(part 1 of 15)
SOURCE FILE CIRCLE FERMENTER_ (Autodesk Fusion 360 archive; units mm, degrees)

design "SOURCE FILE CIRCLE FERMENTER" references "rotary+encoder_14mm_hole_spc", "MODULO RISCALDATORE", "MAGNETE 10x3", "Vite a broccia con testa incassata ed esagono incassato ANSI B18.3.1M - M3x0.5 x 8 Designazione acciaio 2 Radente", "ruthex_RX-M3x4", "GN 1-4 h65.ipt", "Schermo elink", "MODULO RISCALDATORE 1 ventola", "DHT22 Module v3"
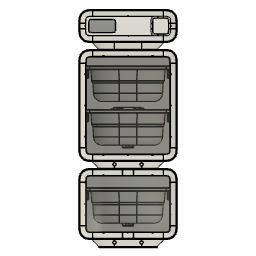
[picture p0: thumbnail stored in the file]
component_insert "Inserimento componente1"
component_insert "Inserimento componente2"
sketch "Schizzo1" plane through (0, 0, 0) normal (0, 0, 1) x axis (1, 0, 0)
  line L1 (-160, 90) -> (160, 90)
  line L2 (-160, -90) -> (-160, 90)
  line L3 (160, -90) -> (-160, -90)
  line L4 (160, 90) -> (160, -90)
  line L5 (-160, -90) -> (160, 90)
  line L6 (160, -90) -> (-160, 90)
  point P6 (0, 0)
  point P1 (0, 0)
  point P3 (-160, 90)
  point P4 (-160, -90)
  horizontal L1
  perpendicular L1 L2
  parallel L1 L3
  parallel L2 L4
  coincident L5 P6
  coincident L6 P6
  coincident P1 P6
  dimension "d1" distance P3 P4 = 180
  dimension "d2" distance L2 L4 = 320
  dimension "TOLL_SPORTELLO" distance = 0.5
extrude "Estrusione1" new body sketch "Schizzo1" profile of L1 L2 L3 L4 along normal blind 116.5 (= "86.50 mm + 30 mm")
extrude "Estrusione2" add of existing geometry blind 88.5 (= "58.50 mm + 30 mm")
sketch "Schizzo1" plane through (160, 0, 0) normal (1, 0, 0) x axis (0, 1, 0)
  line L1 (90, 116.5) -> (90, -88.5)
  line L2 (-90, 116.5) -> (90, 116.5)
  line L3 (-90, -88.5) -> (-90, 116.5)
  line L4 (90, -88.5) -> (-90, -88.5)
  line L5 (0, -88.5) -> (0, 116.5)
  line L6 (-90, 14) -> (90, 14)
  curve K1 (-90, -73.5) -> (-90, -63.5)
  curve K2 (-90, -81) -> (-90, -73.5)
  curve K3 (-82.5, -88.5) -> (-90, -81)
  curve K4 (-75, -88.5) -> (-82.5, -88.5)
  curve K5 (-65, -88.5) -> (-75, -88.5)
  curve K6 (-65, -88.5) -> (-90, -63.5)
  curve K7
  curve K8 (-90, 101.5) -> (-90, 91.5)
  curve K9 (-90, 109) -> (-90, 101.5)
  curve K10 (-82.5, 116.5) -> (-90, 109)
  curve K11 (-75, 116.5) -> (-82.5, 116.5)
  curve K12 (-65, 116.5) -> (-75, 116.5)
  curve K13
  curve K14 (90, 101.5) -> (90, 91.5)
  curve K15 (90, 109) -> (90, 101.5)
  curve K16 (82.5, 116.5) -> (90, 109)
  curve K17 (75, 116.5) -> (82.5, 116.5)
  curve K18 (65, 116.5) -> (75, 116.5)
  curve K19 (65, -88.5) -> (90, -63.5)
  curve K20 (90, -73.5) -> (90, -63.5)
  curve K21 (90, -81) -> (90, -73.5)
  curve K22 (82.5, -88.5) -> (90, -81)
  curve K23 (75, -88.5) -> (82.5, -88.5)
  curve K24 (65, -88.5) -> (75, -88.5)
  line L7 (-90, 91.5) -> (-90, -63.5)
  line L8 (65, 116.5) -> (-65, 116.5)
  line L9 (90, -63.5) -> (90, 91.5)
  line L10 (-65, -88.5) -> (65, -88.5)
  point P6 (0, 116.5)
  point P7 (0, -88.5)
  point P8 (90, 14)
  point P9 (-90, 14)
  point P10 (-90, -63.5)
  point P11 (-90, -73.5)
  point P12 (-90, -81)
  point P13 (-82.5, -88.5)
  point P14 (-75, -88.5)
  point P15 (-65, -88.5)
  point P16 (-90, 91.5)
  point P17 (-65, 116.5)
  point P28 (90, -63.5)
  point P29 (65, -88.5)
  point P22 (90, 91.5)
  point P23 (65, 116.5)
  point P5 (-90, -88.5)
  midpoint L2 P6
  midpoint L4 P7
  midpoint L1 P8
  midpoint L3 P9
  coincident L3 P10
  coincident L3 P11
  coincident L3 P12
  coincident L4 P13
  coincident L4 P14
  coincident L4 P15
  symmetric L6 P10 P16
  symmetric L6 P15 P17
  symmetric L5 P10 P28
  symmetric L5 P15 P29
  symmetric L5 K6 K19
  symmetric L5 P16 P22
  symmetric L5 P17 P23
  symmetric L5 K7 K13
  dimension "d7" distance P5 P13 = 7.5
  dimension "d8" distance P5 P12 = 7.5 (= "d7")
  dimension "d9" distance P5 P14 = 15
  dimension "d10" distance P5 P11 = 15 (= "d9")
  dimension "d11" distance P5 P15 = 25
  dimension "d12" distance P5 P10 = 25 (= "d11")
  dimension "d1108" = 148
extrude "Estrusione1" new body sketch "Schizzo1" profile of K6 K7 K13 K19 L7 L8 L9 L10 against normal blind 320
sketch "Schizzo2" plane through (160, 0, 0) normal (1, 0, 0) x axis (0, 1, 0)
  curve K1 (65, 116.5) -> (90, 91.5)
  line L1 (-65, 116.5) -> (65, 116.5)
  curve K2 (-65, 116.5) -> (-90, 91.5)
  line L2 (-90, -63.5) -> (-90, 91.5)
  curve K3 (-65, -88.5) -> (-90, -63.5)
  line L3 (65, -88.5) -> (-65, -88.5)
  curve K4 (65, -88.5) -> (90, -63.5)
  line L4 (90, 91.5) -> (90, -63.5)
  line L5 (-65, 114.1) -> (65, 114.1)
  curve K5 (-65, 114.1) -> (-87.6, 91.5)
  line L6 (-87.6, -63.5) -> (-87.6, 91.5)
  curve K6 (-65, -86.1) -> (-87.6, -63.5)
  line L7 (65, -86.1) -> (-65, -86.1)
  curve K7 (65, -86.1) -> (87.6, -63.5)
  line L8 (87.6, 91.5) -> (87.6, -63.5)
  curve K8 (65, 114.1) -> (87.6, 91.5)
  dimension "d15" = -2.4
extrude "Estrusione2" cut sketch "Schizzo2" profile of K8 L5 K5 L6 K6 K7 L7 L8 against normal blind 320
sketch "Schizzo3" plane through (0, -90, 0) normal (0, -1, 0) x axis (1, 0, 0)
  line L1 (160, 91.5) -> (160, -63.5)
  line L2 (-160, 91.5) -> (160, 91.5)
  line L3 (-160, -63.5) -> (-160, 91.5)
  line L4 (160, -63.5) -> (-160, -63.5)
  line L5 (-130, 86.5) -> (130, 86.5)
  line L6 (-130, -58.5) -> (-130, 86.5)
  line L7 (130, -58.5) -> (-130, -58.5)
  line L8 (130, 86.5) -> (130, -58.5)
  line L9 (-160, 116.5) -> (160, 116.5)
  line L10 (-160, 91.5) -> (-160, -63.5)
  line L11 (160, 91.5) -> (160, -63.5)
  line L12 (-160, -88.5) -> (160, -88.5)
  horizontal L5
  vertical L6
  horizontal L7
  vertical L8
  dimension "d18" distance L6 L10 = 30
  dimension "d19" distance L5 L9 = 30
  dimension "d20" distance L8 L11 = 30 (= "d18")
  dimension "d21" distance L7 L12 = 30 (= "d19")
extrude "Estrusione3" cut sketch "Schizzo3" profile of L5 L6 L7 L8 against normal blind 331.457
fillet "Raccordo1" radius 22
sketch "Schizzo4" plane through (0, 0, 116.5) normal (0, 0, 1) x axis (-1, 0, 0)
  line L1 (-160, -65) -> (-160, 65)
  line L2 (160, -65) -> (-160, -65)
  line L3 (160, 65) -> (160, -65)
  line L4 (-160, 65) -> (160, 65)
  line L5 (-130, 60) -> (130, 60)
  line L6 (-130, -60) -> (-130, 60)
  line L7 (130, -60) -> (-130, -60)
  line L8 (130, 60) -> (130, -60)
  line L9 (-160, 65) -> (-160, 90)
  line L10 (160, 65) -> (-160, 65)
  line L11 (160, 65) -> (160, 90)
  line L12 (-160, 90) -> (160, 90)
  line L13 (-160, -65) -> (-160, -90)
  line L14 (160, -90) -> (-160, -90)
  line L15 (160, -90) -> (160, -65)
  line L16 (-160, -65) -> (160, -65)
  horizontal L5
  vertical L6
  horizontal L7
  vertical L8
  dimension "d26" distance L3 L8 = 30
  dimension "d29" distance L1 L6 = 30
extrude "Estrusione4" cut sketch "Schizzo4" profile of L2 L4 L5 L6 L7 L8 L10 L16 against normal blind 273.897
fillet "Raccordo2" radius 22
sketch "Schizzo5" plane through (-160, 0, 0) normal (-1, 0, 0) x axis (0, -1, 0)
  curve K1 (-65, 114.1) -> (-87.6, 91.5)
  line L1 (65, 114.1) -> (-65, 114.1)
  curve K2 (87.6, 91.5) -> (65, 114.1)
  line L2 (87.6, -63.5) -> (87.6, 91.5)
  curve K3 (65, -86.1) -> (87.6, -63.5)
  line L3 (-65, -86.1) -> (65, -86.1)
  curve K4 (-87.6, -63.5) -> (-65, -86.1)
  line L4 (-87.6, 91.5) -> (-87.6, -63.5)
  curve K5 (-90, 91.5) -> (-65, 116.5)
  line L5 (-90, -63.5) -> (-90, 91.5)
  curve K6 (-65, -88.5) -> (-90, -63.5)
  line L6 (65, -88.5) -> (-65, -88.5)
  curve K7 (90, -63.5) -> (65, -88.5)
  line L7 (90, 91.5) -> (90, -63.5)
  curve K8 (65, 116.5) -> (90, 91.5)
  line L8 (-65, 116.5) -> (65, 116.5)
  line L9 (-65, 91.5) -> (-65, 114.1)
  line L10 (-87.6, 91.5) -> (-65, 91.5)
  line L11 (-84.5312, 111.0312) -> (-65, 91.5)
  line L12 (-77.8844, 104.3844) -> (-82.8342, 109.3342)
  curve K9 (-80.0057, 102.2631) -> (-77.8844, 104.3844)
  curve K10 (-82.1271, 100.1418) -> (-80.0057, 102.2631)
  curve K11 (-85.6626, 100.8489) -> (-82.1271, 100.1418)
  curve K12 (-87.4513, 97.5) -> (-85.6626, 100.8489)
  curve K13 (-87.577, 94.5) -> (-87.4513, 97.5)
  curve K14 (-87.6, 91.5) -> (-87.577, 94.5)
  curve K15 (-87.6, 91.5) -> (-77.8844, 104.3844)
  line L13 (-90.4063, 91.8626) -> (-77.8844, 104.3844)
  curve K16 (-65, 114.1) -> (-77.8844, 104.3844)
  curve K17 (-75.7631, 106.5057) -> (-77.8844, 104.3844)
  curve K18 (-73.6418, 108.6271) -> (-75.7631, 106.5057)
  curve K19 (-74.3489, 112.1626) -> (-73.6418, 108.6271)
  curve K20 (-71, 113.9513) -> (-74.3489, 112.1626)
  curve K21 (-68, 114.077) -> (-71, 113.9513)
  curve K22 (-65, 114.1) -> (-68, 114.077)
  line L14 (-87.6, 14) -> (87.6, 14)
  line L15 (0, -86.1) -> (0, 114.1)
  curve K23 (65, 114.1) -> (77.8844, 104.3844)
  curve K24 (75.7631, 106.5057) -> (77.8844, 104.3844)
  curve K25 (73.6418, 108.6271) -> (75.7631, 106.5057)
  curve K26 (74.3489, 112.1626) -> (73.6418, 108.6271)
  curve K27 (71, 113.9513) -> (74.3489, 112.1626)
  curve K28 (68, 114.077) -> (71, 113.9513)
  curve K29 (65, 114.1) -> (68, 114.077)
  curve K30 (87.6, 91.5) -> (77.8844, 104.3844)
  curve K31 (80.0057, 102.2631) -> (77.8844, 104.3844)
  curve K32 (82.1271, 100.1418) -> (80.0057, 102.2631)
  curve K33 (85.6626, 100.8489) -> (82.1271, 100.1418)
  curve K34 (87.4513, 97.5) -> (85.6626, 100.8489)
  curve K35 (87.577, 94.5) -> (87.4513, 97.5)
  curve K36 (87.6, 91.5) -> (87.577, 94.5)
  curve K37 (-65, -86.1) -> (-77.8844, -76.3844)
  curve K38 (-75.7631, -78.5057) -> (-77.8844, -76.3844)
  curve K39 (-73.6418, -80.6271) -> (-75.7631, -78.5057)
  curve K40 (-74.3489, -84.1626) -> (-73.6418, -80.6271)
  curve K41 (-71, -85.9513) -> (-74.3489, -84.1626)
  curve K42 (-68, -86.077) -> (-71, -85.9513)
  curve K43 (-65, -86.1) -> (-68, -86.077)
  curve K44 (-87.6, -63.5) -> (-77.8844, -76.3844)
  curve K45 (-80.0057, -74.2631) -> (-77.8844, -76.3844)
  curve K46 (-82.1271, -72.1418) -> (-80.0057, -74.2631)
  curve K47 (-85.6626, -72.8489) -> (-82.1271, -72.1418)
  curve K48 (-87.4513, -69.5) -> (-85.6626, -72.8489)
  curve K49 (-87.577, -66.5) -> (-87.4513, -69.5)
  curve K50 (-87.6, -63.5) -> (-87.577, -66.5)
  curve K51 (65, -86.1) -> (77.8844, -76.3844)
  curve K52 (75.7631, -78.5057) -> (77.8844, -76.3844)
  curve K53 (73.6418, -80.6271) -> (75.7631, -78.5057)
  curve K54 (74.3489, -84.1626) -> (73.6418, -80.6271)
  curve K55 (71, -85.9513) -> (74.3489, -84.1626)
  curve K56 (68, -86.077) -> (71, -85.9513)
  curve K57 (65, -86.1) -> (68, -86.077)
  curve K58 (87.6, -63.5) -> (77.8844, -76.3844)
  curve K59 (80.0057, -74.2631) -> (77.8844, -76.3844)
  curve K60 (82.1271, -72.1418) -> (80.0057, -74.2631)
  curve K61 (85.6626, -72.8489) -> (82.1271, -72.1418)
  curve K62 (87.4513, -69.5) -> (85.6626, -72.8489)
  curve K63 (87.577, -66.5) -> (87.4513, -69.5)
  curve K64 (87.6, -63.5) -> (87.577, -66.5)
  line L16 (-90, 91.5) -> (-87.6, 91.5)
  line L17 (-89.7336, 97.5) -> (-89.7336, 91.5)
  line L18 (-86.7336, 97.5) -> (-89.7336, 97.5)
  point P18 (-65, 114.1)
  point P20 (-65, 114.1)
  point P19 (-87.6, 91.5)
  point P22 (-87.6, 91.5)
  point P23 (-84.5312, 111.0312)
  point P24 (-82.8342, 109.3342)
  point P29 (-87.4513, 97.5)
  point P30 (-87.577, 94.5)
  point P26 (-80.0057, 102.2631)
  point P27 (-82.1271, 100.1418)
  point P2 (-87.6, 91.5)
  point P33 (-65, 114.1)
  point P25 (-77.8844, 104.3844)
  point P32 (-77.8844, 104.3844)
  point P39 (87.6, 14)
  point P40 (-87.6, 14)
  point P41 (0, 114.1)
  point P42 (0, -86.1)
  point P51 (87.6, 91.5)
  point P50 (77.8844, 104.3844)
  point P43 (77.8844, 104.3844)
  point P44 (65, 114.1)
  point P65 (-87.6, -63.5)
  point P64 (-77.8844, -76.3844)
  point P57 (-77.8844, -76.3844)
  point P58 (-65, -86.1)
  point P71 (77.8844, -76.3844)
  point P72 (65, -86.1)
  point P78 (77.8844, -76.3844)
  point P79 (87.6, -63.5)
  point P85 (-87.6, 91.5)
  point P11 (-90, 91.5)
  point P86 (-90, 91.5)
  point P87 (-89.7336, 91.5)
  point P89 (-86.7336, 97.5)
  point P28 (-85.6626, 100.8489)
  point P88 (-89.7336, 97.5)
  coincident P18 P20
  perpendicular L1 L9
  coincident P19 P22
  horizontal L10
  coincident K5 P23
  coincident K1 P24
  coincident L11 P24
  parallel L11 L12
  coincident K1 P29
  coincident K1 P30
  perpendicular L12 L13
  coincident P26 L13
  coincident P27 L13
  symmetric P2 L12 P33
  symmetric P25 L12 P32
  symmetric L12 K15 K16
  midpoint L2 P39
  midpoint L4 P40
  midpoint L1 P41
  midpoint L3 P42
  symmetric P2 L15 P51
  symmetric P25 L15 P50
  symmetric K15 L15 K30
  symmetric P32 L15 P43
  symmetric P33 L15 P44
  symmetric K16 L15 K23
  symmetric P2 L14 P65
  symmetric P25 L14 P64
  symmetric K15 L14 K44
  symmetric P32 L14 P57
  symmetric P33 L14 P58
  symmetric K16 L14 K37
  symmetric L14 P43 P71
  symmetric L14 P44 P72
  symmetric L14 K23 K51
  symmetric L14 P50 P78
  symmetric L14 P51 P79
  symmetric L14 K30 K58
  coincident P2 P85
  coincident P11 P86
  coincident L16 P87
  perpendicular L16 L17
  coincident K15 P89
  perpendicular L17 L18
  dimension "d34" angle L10 L11 = 45
  dimension "d35" distance P24 P25 = 7
  dimension "d38" distance P25 P26 = 3
  dimension "d39" distance P25 P27 = 6
  dimension "d40" distance P28 L13 = 3
  dimension "d41" distance P29 P30 = 3
  dimension "d42" distance P22 P30 = 3
  dimension "d43" distance L11 P28 = 8
  dimension "d57" = 5
  dimension "d172" distance P87 P88 = 6
  dimension "d173" distance P88 P89 = 3
  dimension "d174" distance L4 L17 = 2.1336
  dimension "d209" = 7.5 (= "d208")
  dimension "d210" = 15 (= "d207")
  dimension "d211" = 30 (= "d206")
  dimension "d231" = 7
  dimension "d232" = 5
  dimension "d233" = 5
  dimension "d335" = 5
  dimension "d742" = 9
  dimension "d209_1" = 7.5 (= "d208_1")
  dimension "d210_1" = 15 (= "d207_1")
  dimension "d211_1" = 30 (= "d206_1")
  dimension "d231_1" = 7
  dimension "d232_1" = 5
  dimension "d233_1" = 5
  dimension "d335_1" = 5
  dimension "d742_1" = 9
extrude "Estrusione5" add sketch "Schizzo5" profile of K1 K2 K3 K4 L12 K15 K16 K23 K30 K37 K44 K51 K58 against normal blind 320
sketch "Schizzo7" plane through (160, 0, 0) normal (1, 0, 0) x axis (0, 1, 0)
  line L1 (87.6, -63.5) -> (87.6, 91.5)
  curve K1 (77.8844, -76.3844) -> (87.6, -63.5)
  curve K2 (65, -86.1) -> (77.8844, -76.3844)
  line L2 (-65, -86.1) -> (65, -86.1)
  curve K3 (-77.8844, -76.3844) -> (-65, -86.1)
  curve K4 (-87.6, -63.5) -> (-77.8844, -76.3844)
  line L3 (-87.6, 91.5) -> (-87.6, -63.5)
  curve K5 (-77.8844, 104.3844) -> (-87.6, 91.5)
  curve K6 (-65, 114.1) -> (-77.8844, 104.3844)
  line L4 (65, 114.1) -> (-65, 114.1)
  curve K7 (77.8844, 104.3844) -> (65, 114.1)
  curve K8 (87.6, 91.5) -> (77.8844, 104.3844)
  curve K9 (65, 116.5) -> (90, 91.5)
  line L5 (-65, 116.5) -> (65, 116.5)
  curve K10 (-65, 116.5) -> (-90, 91.5)
  line L6 (-90, -63.5) -> (-90, 91.5)
  curve K11 (-65, -88.5) -> (-90, -63.5)
  line L7 (65, -88.5) -> (-65, -88.5)
  curve K12 (65, -88.5) -> (90, -63.5)
  line L8 (90, 91.5) -> (90, -63.5)
  curve K13 (65, -86.1) -> (87.6, -63.5)
  line L9 (65, -86.1) -> (-65, -86.1)
  curve K14 (-65, -86.1) -> (-87.6, -63.5)
  line L10 (-87.6, -63.5) -> (-87.6, 91.5)
  curve K15 (-65, 114.1) -> (-87.6, 91.5)
  line L11 (-65, 114.1) -> (65, 114.1)
  curve K16 (65, 114.1) -> (87.6, 91.5)
  line L12 (87.6, 91.5) -> (87.6, -63.5)
  dimension "d46" = -2.4
extrude "Estrusione6" cut sketch "Schizzo7" profile of K1 K2 K3 K4 K5 K6 K7 K8 K13 K14 K16 K15 against normal blind 52
work_plane "Piano di lavoro1" AlongDistance -30
sketch "Schizzo8" plane through (0, 0, -58.5) normal (0, 0, -1) x axis (-1, 0, 0)
  line L1 (-130, -38) -> (-130, 38)
  line L2 (-160, -65) -> (-108, -65)
  line L3 (-160, 65) -> (-160, -65)
  line L4 (-108, 65) -> (-160, 65)
  line L5 (-160, -87.6) -> (-160, -65)
  line L6 (-108, -65) -> (-160, -65)
  line L7 (-108, -87.6) -> (-108, -65)
  line L8 (-160, -87.6) -> (-108, -87.6)
  line L9 (-108, -87.6) -> (-108, -65)
  line L10 (-160, -87.6) -> (-108, -87.6)
  line L11 (-134, -82.6) -> (-134, -87.6)
  line L12 (-160, -65) -> (-160, -90)
  line L13 (160, -90) -> (-160, -90)
  line L14 (160, -90) -> (160, -65)
  line L15 (-160, -65) -> (160, -65)
  line L16 (-136.5, -82.6) -> (-134, -82.6)
  line L17 (-131.5, -82.6) -> (-134, -82.6)
  curve K1 (-139, -82.6) -> (-134, -82.6)
  curve K2 (-141.5, -85.1) -> (-139, -82.6)
  curve K3 (-155, -87.6) -> (-141.5, -85.1)
  curve K4 (-160, -87.6) -> (-155, -87.6)
  curve K5 (-160, -87.6) -> (-134, -82.6)
  curve K6 (-108, -87.6) -> (-134, -82.6)
  curve K7 (-129, -82.6) -> (-134, -82.6)
  curve K8 (-126.5, -85.1) -> (-129, -82.6)
  curve K9 (-113, -87.6) -> (-126.5, -85.1)
  curve K10 (-108, -87.6) -> (-113, -87.6)
  line L18 (108, -60) -> (-108, -60)
  line L19 (130, 38) -> (130, -38)
  line L20 (-108, 60) -> (108, 60)
  line L21 (160, 65) -> (-108, 65)
  line L22 (160, -65) -> (160, 65)
  line L23 (-108, -65) -> (160, -65)
  arc A1 centre (-108, 38) radius 22 clockwise from (-130, 38) to (-108, 60)
  arc A2 centre (108, -38) radius 22 clockwise from (130, -38) to (108, -60)
  arc A3 centre (108, 38) radius 22 clockwise from (108, 60) to (130, 38)
  arc A4 centre (-108, -38) radius 22 clockwise from (-108, -60) to (-130, -38)
  point P11 (-108, -65)
  point P15 (-108, -65)
  point P14 (-108, -87.6)
  point P16 (-108, -87.6)
  point P10 (-160, -87.6)
  point P17 (-160, -87.6)
  point P18 (-134, -87.6)
  point P30 (-155, -87.6)
  point P32 (-108, -87.6)
  point P19 (-134, -82.6)
  point P31 (-134, -82.6)
  point P26 (-136.5, -82.6)
  point P27 (-131.5, -82.6)
  point P28 (-139, -82.6)
  point P29 (-141.5, -85.1)
  coincident P11 P15
  coincident P14 P16
  coincident P10 P17
  midpoint L8 P18
  perpendicular L8 L11
  perpendicular L11 L16
  perpendicular L11 L17
  coincident L8 P30
  horizontal K1
  symmetric P10 L11 P32
  symmetric P19 L11 P31
  symmetric L11 K5 K6
  dimension "d50" distance P19 L13 = 7.4
  dimension "d51" distance P19 P26 = 2.5
  dimension "d52" distance P19 P27 = 2.5
  dimension "d53" distance P19 P28 = 5
  dimension "d54" distance P19 P29 = 7.5
  dimension "d55" distance L12 P30 = 5
  dimension "d56" distance L10 P29 = 2.5
  dimension "d57" distance P18 P19 = 5
extrude "Estrusione7" add sketch "Schizzo8" profile of L8 L10 K5 K6 against normal blind 145
work_plane "Piano di lavoro2" AlongDistance -30
sketch "Schizzo9" plane through (0, -60, 0) normal (0, -1, 0) x axis (-1, 0, 0)
  line L1 (-130, 88.5) -> (-108, 88.5)
  line L2 (-160, 88.5) -> (160, 88.5)
  line L3 (160, 88.5) -> (-160, 88.5)
  line L4 (0, 81.1) -> (0, 88.5)
  line L5 (-160, 86.1) -> (-160, 63.5)
  line L6 (-108, 63.5) -> (-160, 63.5)
  line L7 (-108, 86.1) -> (-108, 63.5)
  line L8 (-160, 86.1) -> (-108, 86.1)
  curve K1 (-5, 81.1) -> (0, 81.1)
  curve K2 (-7.5, 83.6) -> (-5, 81.1)
  curve K3 (-155, 86.1) -> (-7.5, 83.6)
  curve K4 (-160, 86.1) -> (-155, 86.1)
  curve K5 (-160, 86.1) -> (0, 81.1)
  curve K6 (160, 86.1) -> (0, 81.1)
  curve K7 (5, 81.1) -> (0, 81.1)
  curve K8 (7.5, 83.6) -> (5, 81.1)
  curve K9 (155, 86.1) -> (7.5, 83.6)
  curve K10 (160, 86.1) -> (155, 86.1)
  line L9 (160, 89.0172) -> (160, 86.1)
  line L10 (154, 89.0172) -> (160, 89.0172)
  line L11 (154, 86.0172) -> (154, 89.0172)
  line L12 (-108, 88.5) -> (108, 88.5)
  line L13 (-130, 88.5) -> (-108, 88.5)
  line L14 (108, 88.5) -> (-108, 88.5)
  line L15 (108, 88.5) -> (130, 88.5)
  line L16 (108, 88.5) -> (130, 88.5)
  point P5 (0, 88.5)
  point P14 (-155, 86.1)
  point P6 (0, 81.1)
  point P15 (0, 81.1)
  point P8 (-160, 86.1)
  point P16 (160, 86.1)
  point P22 (154, 86.0172)
  point P12 (-5, 81.1)
  point P13 (-7.5, 83.6)
  point P20 (160, 89.0172)
  point P21 (154, 89.0172)
  midpoint L3 P5
  perpendicular L3 L4
  coincident L8 P14
  horizontal K1
  symmetric P6 L4 P15
  symmetric L4 P8 P16
  symmetric L4 K5 K6
  perpendicular L2 L9
  perpendicular L9 L10
  coincident K6 P22
  perpendicular L8 L11
  dimension "d61" distance P5 P6 = 7.4
  dimension "d62" distance P6 P12 = 5
  dimension "d63" distance P6 P13 = 7.5
  dimension "d64" distance P13 K1 = 2.5
  dimension "d65" distance P8 P14 = 5
  dimension "d175" distance P20 P21 = 6
  dimension "d176" distance P21 P22 = 3
extrude "Estrusione8" add sketch "Schizzo9" profile of L8 K5 K6 against normal blind 120
extrude "Estrusione9" new body of existing geometry blind 52
sweep "Sweep1" TwistAngle 0 TaperAngle 0
extrude "Estrusione10" cut of existing geometry blind -45
extrude "Estrusione11" new body of existing geometry blind 20
extrude "Estrusione12" new body of existing geometry blind 20
sketch "Schizzo12" plane through (115, 0, 0) normal (1, 0, 0) x axis (0, 1, 0)
  curve K1 (-87.6, -63.5) -> (-65, -86.1)
  curve K2 (-65, -86.1) -> (-77.8844, -76.3844)
  curve K3 (-77.8844, -76.3844) -> (-87.6, -63.5)
  line L1 (-87.6, -38.5) -> (-87.6, -58.5)
  line L2 (-87.6, -58.5) -> (-87.6, -38.5)
  line L3 (-40, -86.1) -> (-60, -86.1)
  line L4 (-60, -86.1) -> (-40, -86.1)
  line L5 (-60, -58.5) -> (-87.6, -58.5)
  line L6 (-60, -86.1) -> (-60, -58.5)
  line L7 (-60, -94.2658) -> (-60, -86.1)
  line L8 (-98.3745, -94.2658) -> (-60, -94.2658)
  line L9 (-98.3745, -58.5) -> (-98.3745, -94.2658)
  line L10 (-87.6, -58.5) -> (-98.3745, -58.5)
  point P5 (-87.6, -58.5)
  point P9 (-87.6, -58.5)
  point P7 (-60, -86.1)
  point P11 (-60, -86.1)
  point P12 (-60, -86.1)
  coincident P5 P9
  perpendicular L1 L5
  coincident P7 P11
  coincident P7 P12
  perpendicular L3 L7
  perpendicular L7 L8
  perpendicular L8 L9
  perpendicular L2 L10
  vertical L6
extrude "Estrusione17" cut sketch "Schizzo12" profile of K1 K2 K3 L5 L6 L7 L8 L9 L10 along normal blind 30
work_plane "Piano di lavoro3" AlongDistance -15
sketch "Schizzo14" plane through (145, 0, 0) normal (1, 0, 0) x axis (0, 1, 0)
  curve K1 (-87.6, -63.5) -> (-65, -86.1)
  curve K2 (-65, -86.1) -> (-77.8844, -76.3844)
  curve K3 (-77.8844, -76.3844) -> (-87.6, -63.5)
  line L1 (-60, -86.1) -> (-60, -85.0993)
  line L2 (60, -86.1) -> (-60, -86.1)
  line L3 (60, -86.1) -> (60, -85.0993)
  line L4 (-87.6, -58.5) -> (-82.6, -58.5)
  line L5 (-82.6, 86.5) -> (-82.6, -58.5)
  line L6 (-82.6, 86.5) -> (-87.6, 86.5)
  line L7 (-87.6, -58.5) -> (-87.6, 86.5)
  curve K4 (-87.6, -63.5) -> (-65, -86.1)
  curve K5 (-82.6, -63.5) -> (-65, -81.1)
  line L8 (-60, -85.0993) -> (60, -85.0993)
  dimension "d98" = 5
loft "Loft2"
sketch "Schizzo15" plane through (145, 0, 0) normal (-1, 0, 0) x axis (0, -1, 0)
  curve K1 (87.3621, -68.5) -> (86.015, -77.3645)
  line L1 (60, -86.1) -> (60, -85.8621)
  line L2 (87.3621, -68.5) -> (87.6, -68.5)
  curve K2 (87.6, -63.5) -> (65, -86.1)
  curve K3 (60, -86.1) -> (61.8352, -86.1277)
  curve K4 (61.8352, -86.1277) -> (70.4705, -86.4786)
  curve K5 (70.4705, -86.4786) -> (78.8782, -85.0557)
  curve K6 (78.8782, -85.0557) -> (86.2494, -77.4051)
  curve K7 (86.2494, -77.4051) -> (87.6, -68.5)
  curve K8 (86.015, -77.3645) -> (78.7154, -84.8822)
  curve K9 (78.7154, -84.8822) -> (70.4157, -86.2471)
  curve K10 (70.4157, -86.2471) -> (61.8337, -85.8898)
  curve K11 (61.8337, -85.8898) -> (60, -85.8621)
extrude "Estrusione20" new body blind 37
step "Inverti normale"
combine "Combina3"
sketch "Schizzo16" plane through (0, 0, 0) normal (0, 0, 1) x axis (1, 0, 0)
  line L1 (145, -87.6) -> (145, -65)
  line L2 (108, -87.6) -> (145, -87.6)
  line L3 (108, -87.6) -> (108, -65)
  line L4 (145, -65) -> (108, -65)
extrude "Estrusione21" new body blind -97.331
step "RitagliaSuperficie1"
step "RitagliaSuperficie2"
sketch "Schizzo17" plane through (145, 0, 0) normal (1, 0, 0) x axis (0, 1, 0)
  line L1 (-87.6, -58.5) -> (-82.6, -58.5)
  curve K1 (-87.6, -63.5) -> (-65, -86.1)
  line L2 (-87.6, -97.331) -> (-87.6, -63.5)
  line L3 (-65, -97.331) -> (-87.6, -97.331)
  line L4 (-65, -86.1) -> (-65, -97.331)
extrude "Estrusione22" new body blind -39.859
step "RitagliaSuperficie3"
step "RitagliaSuperficie4"
surface_stitch "UnisciSuperficie1" StitchingTolerence 0.1
combine "Combina4"
sketch "Schizzo19" plane through (0, 0, 0) normal (0, 0, 1) x axis (1, 0, 0)
  line L1 (130, -60) -> (108, -60)
  line L2 (130, -38) -> (130, -60)
  curve K1 (130, -38) -> (108, -60)
extrude "Estrusione23" cut sketch "Schizzo19" against normal blind 111.944
sketch "Schizzo20" plane through (0, 0, 0) normal (0, 1, 0) x axis (1, 0, 0)
  line L1 (108, 58.5) -> (130, 58.5)
  curve K1 (108, 58.5) -> (130, 36.5)
  line L2 (130, 58.5) -> (130, 36.5)
  line L3 (108, 57.2282) -> (108, 58.5)
  line L4 (130, 36.5) -> (108, 57.2282)
  point P3 (108, 58.5)
  point P5 (108, 58.5)
  point P4 (130, 36.5)
  point P7 (130, 36.5)
  coincident P3 P5
  perpendicular L1 L3
  coincident P4 P7
extrude "Estrusione24" cut sketch "Schizzo20" against normal blind 165.118
sketch "Schizzo21" plane through (0, -90, 0) normal (0, -1, 0) x axis (1, 0, 0)
  line L1 (130, -58.5) -> (130, 64.5)
  line L2 (160, -63.5) -> (-160, -63.5)
  line L3 (160, 91.5) -> (160, -63.5)
  line L4 (-160, 91.5) -> (160, 91.5)
  curve K1 (108, 86.5) -> (130, 64.5)
  line L5 (-160, -63.5) -> (-160, -88.5)
  line L6 (160, -88.5) -> (-160, -88.5)
  line L7 (160, -88.5) -> (160, -63.5)
  line L8 (-160, -63.5) -> (160, -63.5)
  curve K2 (130, -43.5) -> (130, -28.5)
  curve K3 (130, -51) -> (130, -43.5)
  curve K4 (122.5, -58.5) -> (130, -51)
  curve K5 (115, -58.5) -> (122.5, -58.5)
  curve K6 (100, -58.5) -> (115, -58.5)
  curve K7 (100, -58.5) -> (130, -28.5)
  line L9 (-160, -63.5) -> (-160, 91.5)
  line L10 (-108, -58.5) -> (130, -58.5)
  curve K8 (-108, -58.5) -> (-130, -36.5)
  line L11 (-130, 64.5) -> (-130, -36.5)
  curve K9 (-130, 64.5) -> (-108, 86.5)
  line L12 (108, 86.5) -> (-108, 86.5)
  point P13 (130, -28.5)
  point P14 (130, -43.5)
  point P15 (130, -51)
  coincident L1 P13
  coincident L1 P14
  coincident L1 P15
  dimension "d111" = 30
  dimension "d112" = 7.5
  dimension "d113" = 7.5 (= "d112")
  dimension "d114" = 15 (= "d116")
  dimension "d115" = 30 (= "d111")
  dimension "d116" = 15
extrude "Estrusione25" add sketch "Schizzo21" profile of L1 K7 against normal blind 2.4
sketch "Schizzo22" plane through (0, 0, -88.5) normal (0, 0, -1) x axis (1, 0, 0)
  line L1 (130, -38) -> (130, 60)
  line L2 (160, -65) -> (-160, -65)
  line L3 (160, 65) -> (160, -65)
  line L4 (-160, 65) -> (160, 65)
  line L5 (-160, 90) -> (-160, 65)
  line L6 (160, 65) -> (-160, 65)
  line L7 (160, 65) -> (160, 90)
  line L8 (-160, 90) -> (160, 90)
  curve K1 (115, 65.2426) -> (-130.0531, 66.7836)
  curve K2 (-152.5039, 65.2426) -> (115, 65.2426)
  curve K3 (130, 52.5) -> (-152.5039, 65.2426)
  curve K4 (130, 45) -> (130, 52.5)
  curve K5 (130, 30) -> (130, 45)
  curve K6 (130, 30) -> (-130.0531, 66.7836)
  line L9 (-108, -60) -> (108, -60)
  line L10 (-130, 38) -> (-130, -38)
  line L11 (130, 60) -> (-108, 60)
  line L12 (-160, -65) -> (-160, 65)
  arc A1 centre (108, -38) radius 22 clockwise from (130, -38) to (108, -60)
  arc A2 centre (-108, -38) radius 22 clockwise from (-108, -60) to (-130, -38)
  arc A3 centre (-108, 38) radius 22 clockwise from (-130, 38) to (-108, 60)
  point P17 (130, 52.5)
  point P18 (130, 45)
  point P19 (130, 30)
  point P2 (130, 60)
  point P11 (-160, 65)
  point P16 (-152.5039, 65.2426)
  point P15 (115, 65.2426)
  point P14 (-130.0531, 66.7836)
  coincident L1 P17
  coincident L1 P18
  coincident L1 P19
  horizontal K2
  dimension "d125" distance P2 P17 = 7.5
  dimension "d126" distance P11 P16 = 7.5 (= "d125")
  dimension "d127" distance P2 P18 = 15
  dimension "d128" distance P2 P15 = 15 (= "d127")
  dimension "d129" distance P2 P19 = 30
  dimension "d130" distance P11 P14 = 30 (= "d129")
extrude "Estrusione26" add sketch "Schizzo22" profile of L1 K6 against normal blind 2.4
work_plane "Piano di lavoro4" AlongDistance -4.6 (= "-3 mm - 1.6 mm")
sketch "Schizzo25" plane through (0, 0, -83.9) normal (0, 0, -1) x axis (-1, 0, 0)
  line L1 (-108, -72.7071) -> (160, -72.7071)
  line L2 (-136.9983, 60) -> (-136.9983, -60)
  line L3 (160, 60) -> (-136.9983, 60)
  line L4 (160, -72.7071) -> (160, 60)
  line L5 (-124.9983, -72.7071) -> (-108, -72.7071)
  line L6 (-136.9983, -60) -> (-136.9983, -60.7071)
  arc A1 centre (-124.9983, -60.7071) radius 12 clockwise from (-124.9983, -72.7071) to (-136.9983, -60.7071)
  point P5 (-136.9983, 60)
  point P6 (-136.9983, 60)
  point P2 (160, -72.7071)
  point P8 (160, -72.7071)
  point P3 (-108, -72.7071)
  point P9 (-108, -72.7071)
  point P4 (-136.9983, -60)
  point P10 (-136.9983, -60)
  coincident P5 P6
  perpendicular L2 L3
  coincident P2 P8
  vertical L4
  coincident P3 P9
  parallel L1 L5
  coincident P4 P10
  vertical L6
  tangent L6 A1
  tangent L5 A1
  dimension "d151" radius A1 = 12
sketch "Schizzo27" plane through (0, 0, 116.5) normal (0, 0, 1) x axis (-1, 0, 0)
  line L1 (-130, 38) -> (-130, -38)
  line L2 (-160, 65) -> (160, 65)
  line L3 (-160, -65) -> (-160, 65)
  line L4 (160, -65) -> (-160, -65)
  line L5 (-251.3279, 157.4201) -> (287.4424, 157.4201)
  line L6 (-251.3279, -160.7695) -> (-251.3279, 157.4201)
  line L7 (287.4424, -160.7695) -> (-251.3279, -160.7695)
  line L8 (287.4424, 157.4201) -> (287.4424, -160.7695)
  line L9 (108, 60) -> (-108, 60)
  line L10 (130, -38) -> (130, 38)
  line L11 (-108, -60) -> (108, -60)
  line L12 (160, 65) -> (160, -65)
  arc A1 centre (-108, -38) radius 22 clockwise from (-108, -60) to (-130, -38)
  arc A2 centre (108, 38) radius 22 clockwise from (108, 60) to (130, 38)
  arc A3 centre (108, -38) radius 22 clockwise from (130, -38) to (108, -60)
  arc A4 centre (-108, 38) radius 22 clockwise from (-130, 38) to (-108, 60)
  horizontal L5
  vertical L6
  horizontal L7
  vertical L8
extrude "Estrusione35" cut sketch "Schizzo27" profile of L1 L2 L3 L4 A1 L5 L6 L7 L8 against normal blind 30
extrude "Estrusione36" cut of existing geometry blind -200
sketch "Schizzo28" plane through (0, 90, 0) normal (0, 1, 0) x axis (-1, 0, 0)
  line L1 (-130, 64.5) -> (-130, -36.5)
  curve K1 (-130, 64.5) -> (-108, 86.5)
  line L2 (-160, 86.5) -> (-108, 86.5)
  line L3 (-160, -63.5) -> (-160, 86.5)
  line L4 (-40, -63.5) -> (-160, -63.5)
  line L5 (17.9927, 118.9974) -> (-225.318, 118.9974)
  line L6 (17.9927, -128.8116) -> (17.9927, 118.9974)
  line L7 (-225.318, -128.8116) -> (17.9927, -128.8116)
  line L8 (-225.318, 118.9974) -> (-225.318, -128.8116)
  line L9 (-40, -58.5) -> (-40, -63.5)
  line L10 (-108, -58.5) -> (-40, -58.5)
  curve K2 (-108, -58.5) -> (-130, -36.5)
  horizontal L5
  vertical L6
  horizontal L7
  vertical L8
extrude "Estrusione37" cut sketch "Schizzo28" profile of L1 K1 L2 L3 L4 L5 L6 L7 L8 against normal blind 80
sketch "Schizzo29" plane through (0, 0, -86.1) normal (0, 0, 1) x axis (-1, 0, 0)
  line L1 (-108, 65) -> (-40, 65)
  curve K1 (-40, 55.8192) -> (-108, 44.7571)
  line L2 (-40, 77.8844) -> (-40, 65)
  line L3 (-108, 77.8844) -> (-40, 77.8844)
  line L4 (-40, 65) -> (-108, 65)
  line L5 (-130, 30) -> (-130, -10)
  line L6 (-130, -10) -> (-145, -10)
  line L7 (-130, 30) -> (-130, -10)
  line L8 (-130, 60) -> (-130, 30)
  line L9 (-130, 60) -> (-145, 60)
  line L10 (-145, -10) -> (-145, 60)
  curve K2 (-40, 55.8192) -> (-108, 44.7571)
  line L11 (-130, -10) -> (-130, 30)
  line L12 (-40, 60) -> (-100, 60)
  line L13 (-40, 60) -> (-40, 66)
  line L14 (-130, -10) -> (-124, -10)
  line L15 (-40, 65) -> (-40, 55.8192)
  line L16 (-108, 60) -> (-108, 65)
  line L17 (-108, 44.7571) -> (-108, 60)
  line L18 (-108, 71.2518) -> (-108, 77.8844)
  line L19 (-108, 70.3697) -> (-108, 71.2518)
  line L20 (-108, 65) -> (-108, 70.3697)
  curve K3 (-40.8263, 61.7621) -> (-109.393, 50.5931)
  line L21 (-124, -10) -> (-124, 30)
  line L22 (-40, 66) -> (-100, 66)
  point P20 (-40, 60)
  point P23 (-40, 60)
  point P19 (-130, -10)
  point P24 (-130, -10)
  coincident P20 P23
  perpendicular L12 L13
  coincident P19 P24
  perpendicular L5 L14
  dimension "d158" = -6
sketch "Schizzo30" plane through (160, 0, 0) normal (1, 0, 0) x axis (0, 1, 0)
  line L1 (10, -86.1) -> (10, -88.5)
  line L2 (-60, -86.1) -> (10, -86.1)
  line L3 (-87.6, 86.5) -> (-87.6, -58.5)
  line L4 (-90, 86.5) -> (-87.6, 86.5)
  line L5 (-90, -63.5) -> (-90, 86.5)
  curve K1 (-65, -88.5) -> (-90, -63.5)
  line L6 (10, -88.5) -> (-65, -88.5)
  line L7 (-91.8, -63.5) -> (-91.8, 86.5)
  curve K2 (-65, -90.3) -> (-91.8, -63.5)
  line L8 (10, -90.3) -> (-65, -90.3)
  line L9 (-91.8, 86.5) -> (-90, 86.5)
  line L10 (10, -90.3) -> (10, -88.5)
  line L11 (-65, -86.1) -> (-60, -86.1)
  curve K3 (-87.6, -63.5) -> (-65, -86.1)
  line L12 (-87.6, -58.5) -> (-87.6, -63.5)
  point P7 (-90, 86.5)
  point P14 (-90, 86.5)
  point P2 (10, -88.5)
  point P15 (10, -88.5)
  coincident P7 P14
  perpendicular L7 L9
  coincident P2 P15
  perpendicular L8 L10
  dimension "d163" = 1.8
sketch "Schizzo1" plane through (160, 0, 0) normal (1, 0, 0) x axis (0, 1, 0)
  line L1 (90, 116.5) -> (90, -88.5)
  line L2 (-90, 116.5) -> (90, 116.5)
  line L3 (-90, -88.5) -> (-90, 116.5)
  line L4 (90, -88.5) -> (-90, -88.5)
  curve K1 (-65, -88.5) -> (-90, -63.5)
  line L5 (-15, -88.5) -> (-65, -88.5)
  line L6 (-90, -13.5) -> (-90, -63.5)
  line L7 (-15, -86.9) -> (-65, -86.9)
  curve K2 (-65, -86.9) -> (-88.4, -63.5)
  line L8 (-88.4, -13.5) -> (-88.4, -63.5)
  line L9 (-15, -88.5) -> (-15, -86.9)
  line L10 (-88.4, -13.5) -> (-90, -13.5)
  point P7 (-65, -88.5)
  point P8 (-65, -88.5)
  point P6 (-90, -63.5)
  point P10 (-90, -63.5)
  point P9 (-15, -88.5)
  point P11 (-90, -13.5)
  coincident P7 P8
  parallel L4 L5
  coincident P6 P10
  parallel L3 L6
  perpendicular L5 L9
  dimension "d178" distance P8 P9 = 50
  dimension "d179" distance P10 P11 = 50
  dimension "d180" = -1.6
extrude "Estrusione1" new body sketch "Schizzo1" profile of L3 L4 K1 L5 L6 L7 K2 L8 L9 L10 against normal blind 120
sketch "Schizzo2" plane through (0, 0, -88.5) normal (0, 0, -1) x axis (1, 0, 0)
  line L1 (160, 65) -> (160, 15)
  line L2 (40, 65) -> (160, 65)
  line L3 (40, 15) -> (40, 65)
  line L4 (160, 15) -> (40, 15)
  line L5 (125, 15) -> (40, 15)
  line L6 (125, 55) -> (125, 15)
  line L7 (40, 55) -> (125, 55)
  line L8 (40, 15) -> (40, 55)
  line L9 (160, 65) -> (160, 90)
  line L10 (40, 90) -> (160, 90)
  line L11 (40, 90) -> (40, 65)
  line L12 (160, 65) -> (40, 65)
  point P5 (40, 15)
  point P6 (40, 15)
  horizontal L5
  vertical L6
  horizontal L7
  vertical L8
  coincident P5 P6
  dimension "d183" distance L1 L6 = 35
  dimension "d184" distance L7 L10 = 35
extrude "Estrusione2" cut sketch "Schizzo2" profile of L3 L4 L5 L6 L7 L8 against normal blind 2.4
sketch "Schizzo3" plane through (0, 0, -86.9) normal (0, 0, 1) x axis (-1, 0, 0)
  line L1 (-40, 55) -> (-125, 55)
  line L2 (-40, 65) -> (-40, 55)
  line L3 (-160, 65) -> (-40, 65)
  line L4 (-160, 15) -> (-160, 65)
  line L5 (-125, 15) -> (-160, 15)
  line L6 (-125, 55) -> (-125, 15)
  line L7 (-135, 65) -> (-40, 65)
  line L8 (-135, 15) -> (-135, 65)
  line L9 (-40, 15) -> (-135, 15)
  line L10 (-40, 65) -> (-40, 15)
  point P10 (-135, 15)
  point P4 (-40, 65)
  point P8 (-40, 65)
  horizontal L7
  vertical L8
  horizontal L9
  vertical L10
  coincident L5 P10
  coincident P4 P8
  dimension "d187" distance L6 L8 = 10
  dimension "d188" distance L1 L7 = 10
extrude "Estrusione3" new body sketch "Schizzo3" profile of L1 L2 L3 L5 L6 L7 L8 L9 L10 along normal blind 3 bodies "TEST ACRILICO"
sketch "Schizzo4" plane through (0, -90, 0) normal (0, -1, 0) x axis (1, 0, 0)
  line L1 (160, -13.5) -> (160, -63.5)
  line L2 (40, -13.5) -> (160, -13.5)
  line L3 (40, -63.5) -> (40, -13.5)
  line L4 (160, -63.5) -> (40, -63.5)
  line L5 (160, -88.5) -> (160, -63.5)
  line L6 (40, -63.5) -> (160, -63.5)
  line L7 (40, -63.5) -> (40, -88.5)
  line L8 (160, -88.5) -> (40, -88.5)
  line L9 (125, -13.5) -> (40, -13.5)
  line L10 (125, -53.5) -> (125, -13.5)
  line L11 (40, -53.5) -> (125, -53.5)
  line L12 (40, -13.5) -> (40, -53.5)
  point P4 (40, -13.5)
  point P10 (40, -13.5)
  horizontal L9
  vertical L10
  horizontal L11
  vertical L12
  coincident P4 P10
  dimension "d191" distance L1 L10 = 35
  dimension "d192" distance L8 L11 = 35
extrude "Estrusione4" cut sketch "Schizzo4" profile of L2 L3 L9 L10 L11 L12 against normal blind 14.667
sketch "Schizzo5" plane through (0, -88.4, 0) normal (0, 1, 0) x axis (-1, 0, 0)
  line L1 (-125, -53.5) -> (-40, -53.5)
  line L2 (-125, -13.5) -> (-125, -53.5)
  line L3 (-160, -13.5) -> (-125, -13.5)
  line L4 (-160, -63.5) -> (-160, -13.5)
  line L5 (-40, -63.5) -> (-160, -63.5)
  line L6 (-40, -53.5) -> (-40, -63.5)
  line L7 (-135, -63.5) -> (-40, -63.5)
  line L8 (-135, -13.5) -> (-135, -63.5)
  line L9 (-40, -13.5) -> (-135, -13.5)
  line L10 (-40, -63.5) -> (-40, -13.5)
  point P10 (-135, -13.5)
  point P7 (-40, -63.5)
  point P8 (-40, -63.5)
  horizontal L7
  vertical L8
  horizontal L9
  vertical L10
  coincident L3 P10
  coincident P7 P8
  dimension "d195" distance L2 L8 = 10
extrude "Estrusione5" new body sketch "Schizzo5" profile of L1 L2 L3 L5 L6 L7 L8 L9 L10 along normal blind 3 bodies "TEST ACRILICO 2"
sketch "Schizzo6" plane through (0, -90, 0) normal (0, -1, 0) x axis (1, 0, 0)
  line L1 (40, -53.5) -> (125, -53.5)
  line L2 (40, -63.5) -> (40, -53.5)
  line L3 (160, -63.5) -> (40, -63.5)
  line L4 (160, -13.5) -> (160, -63.5)
  line L5 (125, -13.5) -> (160, -13.5)
  line L6 (125, -53.5) -> (125, -13.5)
  curve K1 (110, -53.5) -> (95, -53.5)
  curve K2 (117.5, -53.5) -> (110, -53.5)
  curve K3 (125, -46) -> (117.5, -53.5)
  curve K4 (125, -38.5) -> (125, -46)
  curve K5 (125, -23.5) -> (125, -38.5)
  curve K6 (125, -23.5) -> (95, -53.5)
  point P8 (95, -53.5)
  point P9 (110, -53.5)
  point P10 (117.5, -53.5)
  point P11 (125, -46)
  point P12 (125, -38.5)
  point P13 (125, -23.5)
  point P2 (125, -53.5)
  coincident L1 P8
  coincident L1 P9
  coincident L1 P10
  coincident L6 P11
  coincident L6 P12
  coincident L6 P13
  dimension "d198" distance P2 P8 = 30
  dimension "d199" distance P2 P9 = 15
  dimension "d200" distance P2 P10 = 7.5
  dimension "d201" distance P2 P11 = 7.5 (= "d200")
  dimension "d202" distance P2 P12 = 15 (= "d199")
  dimension "d203" distance P2 P13 = 30 (= "d198")
extrude "Estrusione6" add sketch "Schizzo6" profile of L1 L6 K6 against normal blind 1.6
sketch "Schizzo7" plane through (0, 0, -88.5) normal (0, 0, -1) x axis (1, 0, 0)
  line L1 (125, 55) -> (40, 55)
  line L2 (125, 15) -> (125, 55)
  line L3 (160, 15) -> (125, 15)
  line L4 (160, 65) -> (160, 15)
  line L5 (40, 65) -> (160, 65)
  line L6 (40, 55) -> (40, 65)
  curve K1 (125, 40) -> (125, 25)
  curve K2 (125, 47.5) -> (125, 40)
  curve K3 (117.5, 55) -> (125, 47.5)
  curve K4 (110, 55) -> (117.5, 55)
  curve K5 (95, 55) -> (110, 55)
  curve K6 (95, 55) -> (125, 25)
  point P8 (125, 25)
  point P9 (125, 40)
  point P10 (125, 47.5)
  point P11 (117.5, 55)
  point P12 (110, 55)
  point P13 (95, 55)
  point P3 (125, 55)
  coincident L2 P8
  coincident L2 P9
  coincident L2 P10
  coincident L1 P11
  coincident L1 P12
  coincident L1 P13
  dimension "d206" distance P3 P13 = 30
  dimension "d207" distance P3 P12 = 15
  dimension "d208" distance P3 P11 = 7.5
  dimension "d209" distance P3 P10 = 7.5 (= "d208")
  dimension "d210" distance P3 P9 = 15 (= "d207")
  dimension "d211" distance P3 P8 = 30 (= "d206")
extrude "Estrusione7" add sketch "Schizzo7" profile of L1 L2 K6 against normal blind 1.6
sketch "Schizzo8" plane through (0, 0, -83.9) normal (0, 0, 1) x axis (-1, 0, 0)
  line L1 (-40, 65) -> (-40, 15)
  line L2 (-135, 65) -> (-40, 65)
  line L3 (-135, 15) -> (-135, 65)
  line L4 (-40, 15) -> (-135, 15)
  curve K1 (-95, 55) -> (-125, 25)
  curve K2 (-95, 65) -> (-135, 25)
  line L5 (-135, 15) -> (-135, 25)
  line L6 (-40, 65) -> (-95, 65)
  point P3 (-40, 65)
  point P11 (-40, 65)
  perpendicular L4 L5
  coincident P3 P11
  dimension "d214" = -10
extrude "Estrusione8" cut sketch "Schizzo8" profile of L2 L3 K2 against normal blind 3
sketch "Schizzo9" plane through (0, -85.4, 0) normal (0, 1, 0) x axis (-1, 0, 0)
  line L1 (-135, -13.5) -> (-40, -13.5)
  line L2 (-135, -63.5) -> (-135, -13.5)
  line L3 (-40, -63.5) -> (-135, -63.5)
  line L4 (-40, -13.5) -> (-40, -63.5)
  curve K1 (-125, -23.5) -> (-95, -53.5)
  curve K2 (-135, -23.5) -> (-95, -63.5)
  dimension "d217" = -10
extrude "Estrusione9" cut sketch "Schizzo9" profile of L2 L3 K2 against normal blind 3
sketch "Schizzo10" plane through (160, 0, 0) normal (1, 0, 0) x axis (0, 1, 0)
  curve K1 (-65, -88.5) -> (-90, -63.5)
  line L1 (-15, -88.5) -> (-65, -88.5)
  line L2 (-15, -86.9) -> (-15, -88.5)
  line L3 (-65, -86.9) -> (-15, -86.9)
  curve K2 (-65, -86.9) -> (-88.4, -63.5)
  line L4 (-88.4, -13.5) -> (-88.4, -63.5)
  line L5 (-90, -13.5) -> (-88.4, -13.5)
  line L6 (-90, -63.5) -> (-90, -13.5)
  line L7 (-25, -83.9) -> (-65, -83.9)
  line L8 (-65, -86.9) -> (-65, -83.9)
  line L9 (-65, -86.9) -> (-25, -86.9)
  line L10 (-25, -83.9) -> (-25, -86.9)
  line L11 (-85.4, -63.5) -> (-85.4, -23.5)
  line L12 (-88.4, -23.5) -> (-85.4, -23.5)
  line L13 (-88.4, -23.5) -> (-88.4, -63.5)
  line L14 (-85.4, -63.5) -> (-88.4, -63.5)
  line L15 (-90, -88.5) -> (-65, -88.5)
  line L16 (-90, -63.5) -> (-90, -88.5)
  line L17 (-63.3232, -61.8232) -> (-90, -88.5)
  line L18 (-78.4501, -76.9501) -> (-83.3998, -81.8998)
  curve K3 (-65, -83.9) -> (-85.4, -63.5)
  line L19 (-70.5446, -84.8556) -> (-78.4501, -76.9501)
  curve K4 (-74.9146, -80.4856) -> (-78.4501, -76.9501)
  curve K5 (-74.9146, -83.3141) -> (-74.9146, -80.4856)
  curve K6 (-69, -83.8545) -> (-74.9146, -83.3141)
  curve K7 (-65, -83.9) -> (-69, -83.8545)
  curve K8 (-65, -83.9) -> (-78.4501, -76.9501)
  curve K9 (-85.4, -63.5) -> (-78.4501, -76.9501)
  curve K10 (-81.9856, -73.4146) -> (-78.4501, -76.9501)
  curve K11 (-84.8141, -73.4146) -> (-81.9856, -73.4146)
  curve K12 (-85.3545, -67.5) -> (-84.8141, -73.4146)
  curve K13 (-85.4, -63.5) -> (-85.3545, -67.5)
  point P3 (-65, -88.5)
  point P18 (-65, -88.5)
  point P2 (-90, -63.5)
  point P20 (-90, -63.5)
  point P22 (-83.3998, -81.8998)
  point P23 (-78.4501, -76.9501)
  point P27 (-74.9146, -80.4856)
  point P29 (-69, -83.8545)
  point P10 (-65, -83.9)
  point P25 (-65, -83.9)
  point P31 (-85.4, -63.5)
  point P30 (-78.4501, -76.9501)
  point P28 (-74.9146, -83.3141)
  coincident P3 P18
  coincident P2 P20
  vertical L16
  coincident L17 P22
  coincident K2 P22
  coincident L17 P23
  perpendicular L18 L19
  coincident L19 P27
  coincident K3 P29
  coincident P10 P25
  symmetric P10 L17 P31
  symmetric L17 P23 P30
  symmetric L17 K8 K9
  dimension "d220" angle L15 L17 = 45
  dimension "d221" distance P22 P23 = 7
  dimension "d222" = -3
  dimension "d223" distance P27 P30 = 5
  dimension "d224" distance L19 P28 = 2
  dimension "d225" distance P25 P29 = 4
  dimension "d228" distance L17 P28 = 7
extrude "Estrusione10" add sketch "Schizzo10" profile of K2 L8 L14 L18 K8 K9 against normal blind 120
extrude "Estrusione11" cut sketch "Schizzo10" profile of K2 L8 L14 L18 K8 K9 against normal blind 65
sketch "Schizzo11" plane through (0, 0, -13.5) normal (0, 0, 1) x axis (-1, 0, 0)
  line L1 (-125, 90) -> (-125, 88.4)
  line L2 (-160, 90) -> (-125, 90)
  line L3 (-160, 88.4) -> (-160, 90)
  line L4 (-125, 88.4) -> (-160, 88.4)
  line L5 (-135, 88.4) -> (-40, 88.4)
  line L6 (-135, 85.4) -> (-135, 88.4)
  line L7 (-40, 85.4) -> (-135, 85.4)
  line L8 (-40, 88.4) -> (-40, 85.4)
  line L9 (-142.5, 81.4) -> (-142.5, 88.4)
  line L10 (-147.5, 81.4) -> (-142.5, 81.4)
  line L11 (-137.5, 81.4) -> (-142.5, 81.4)
  curve K1 (-154.5, 88.4) -> (-160, 88.4)
  curve K2 (-148.5, 84.9) -> (-154.5, 88.4)
  curve K3 (-146.5, 81.4) -> (-148.5, 84.9)
  curve K4 (-142.5, 81.4) -> (-146.5, 81.4)
  curve K5 (-142.5, 81.4) -> (-160, 88.4)
  curve K6 (-139.5, 81.4) -> (-142.5, 81.4)
  curve K7 (-139, 84.9) -> (-139.5, 81.4)
  curve K8 (-137, 85.4) -> (-139, 84.9)
  curve K9 (-135, 85.4) -> (-137, 85.4)
  curve K10 (-135, 85.4) -> (-142.5, 81.4)
  point P10 (-142.5, 88.4)
  point P14 (-154.5, 88.4)
  point P16 (-146.5, 81.4)
  point P17 (-139.5, 81.4)
  point P11 (-142.5, 81.4)
  point P12 (-147.5, 81.4)
  point P13 (-137.5, 81.4)
  point P15 (-148.5, 84.9)
  point P8 (-135, 85.4)
  point P19 (-137, 85.4)
  point P18 (-139, 84.9)
  midpoint L4 P10
  perpendicular L4 L9
  perpendicular L9 L10
  perpendicular L9 L11
  coincident L4 P14
  coincident L10 P16
  coincident L11 P17
  horizontal K9
  dimension "d231" distance P10 P11 = 7
  dimension "d232" distance P11 P12 = 5
  dimension "d233" distance P11 P13 = 5
  dimension "d234" distance L9 P14 = 12
  dimension "d235" distance L9 P15 = 6
  dimension "d236" distance L9 P16 = 4
  dimension "d237" distance L10 P15 = 3.5
  dimension "d238" distance P11 P17 = 3
  dimension "d239" distance P8 P19 = 2
  dimension "d240" distance L6 P18 = 4
  dimension "d241" distance L11 P18 = 3.5
extrude "Estrusione12" add sketch "Schizzo11" profile of L4 L6 K5 K10 against normal blind 50
work_plane "Piano di lavoro1"
mirror "Specchio1" mirrorStitchTolerance 0.1
sketch "Schizzo12" plane through (0, 0, -86.9) normal (0, 0, 1) x axis (-1, 0, 0)
  line L1 (-135, 15) -> (-135, 65)
  line L2 (-125, 15) -> (-135, 15)
  line L3 (-125, 25) -> (-125, 15)
  curve K1 (-95, 55) -> (-125, 25)
  line L4 (-40, 55) -> (-95, 55)
  line L5 (-40, 65) -> (-40, 55)
  line L6 (-95, 65) -> (-40, 65)
  line L7 (-135, 65) -> (-95, 65)
  curve K2 (-135, 25) -> (-95, 65)
  line L8 (-135, 15) -> (-135, 25)
  line L9 (-40, 15) -> (-135, 15)
  line L10 (-40, 65) -> (-40, 15)
  line L11 (-95, 65) -> (-40, 65)
extrude "Estrusione13" new body sketch "Schizzo12" profile of L1 L7 K2 along normal blind 3
sketch "Schizzo13" plane through (0, -88.4, 0) normal (0, 1, 0) x axis (-1, 0, 0)
  line L1 (-135, -63.5) -> (-135, -13.5)
  line L2 (-95, -63.5) -> (-135, -63.5)
  line L3 (-40, -63.5) -> (-95, -63.5)
  line L4 (-40, -53.5) -> (-40, -63.5)
  line L5 (-95, -53.5) -> (-40, -53.5)
  curve K1 (-125, -23.5) -> (-95, -53.5)
  line L6 (-125, -13.5) -> (-125, -23.5)
  line L7 (-135, -13.5) -> (-125, -13.5)
  curve K2 (-95, -63.5) -> (-135, -23.5)
  line L8 (-40, -63.5) -> (-95, -63.5)
  line L9 (-40, -13.5) -> (-40, -63.5)
  line L10 (-135, -13.5) -> (-40, -13.5)
  line L11 (-135, -23.5) -> (-135, -13.5)
extrude "Estrusione14" new body sketch "Schizzo13" profile of L1 L2 K2 along normal blind 3
combine "Combina1"
sketch "Schizzo14" plane through (0, -65, 0) normal (0, -1, 0) x axis (1, 0, 0)
  curve K1 (160, -86.9) -> (142.5, -79.9)
  curve K2 (142.5, -79.9) -> (135, -83.9)
  line L1 (95, -83.9) -> (135, -83.9)
  line L2 (95, -86.9) -> (95, -83.9)
  line L3 (160, -86.9) -> (95, -86.9)
  line L4 (125, -86.9) -> (125, -88.5)
  line L5 (135, -86.9) -> (125, -86.9)
  line L6 (135, -83.9) -> (135, -86.9)
  curve K3 (135, -83.9) -> (142.5, -79.9)
  curve K4 (142.5, -79.9) -> (160, -86.9)
  line L7 (160, -88.5) -> (160, -86.9)
  line L8 (125, -88.5) -> (160, -88.5)
  line L9 (142.5, -86.9) -> (142.5, -79.9)
  line L10 (160, -86.9) -> (142.5, -86.9)
  point P11 (142.5, -79.9)
  point P14 (142.5, -79.9)
  point P15 (142.5, -86.9)
  point P12 (160, -86.9)
  point P16 (160, -86.9)
  coincident P11 P14
  coincident L3 P15
  perpendicular L3 L9
  coincident P12 P16
sweep "Sweep1" sketch "Schizzo14" TwistAngle 0 TaperAngle 0
combine "Combina2"
extrude "Estrusione15" add of existing geometry blind 15
loft "Loft1"
extrude "Estrusione16" new body of existing geometry blind 32.5
surface_patch "ChiusuraSuperficie1"
step "Separa1"
surface_delete_face "FacciaEliminazioneSuperficie1"
surface_delete_face "FacciaEliminazioneSuperficie2"
surface_delete_face "FacciaEliminazioneSuperficie3"
surface_delete_face "FacciaEliminazioneSuperficie4"
extrude "Estrusione17" new body of existing geometry blind 32.5
surface_patch "ChiusuraSuperficie2"
surface_delete_face "FacciaEliminazioneSuperficie5"
step "RitagliaSuperficie1"
surface_stitch "UnisciSuperficie1" StitchingTolerence 0.1
surface_delete_face "FacciaEliminazioneSuperficie6"
combine "Combina3"
sketch "Schizzo15" plane through (40, 0, 0) normal (-1, 0, 0) x axis (0, -1, 0)
  line L1 (88.4, -53.5) -> (90, -53.5)
  line L2 (88.4, -63.5) -> (88.4, -53.5)
  line L3 (85.4, -63.5) -> (88.4, -63.5)
  curve K1 (78.4501, -76.9501) -> (85.4, -63.5)
  curve K2 (65, -83.9) -> (78.4501, -76.9501)
  line L4 (65, -86.9) -> (65, -83.9)
  line L5 (55, -86.9) -> (65, -86.9)
  line L6 (55, -88.5) -> (55, -86.9)
  line L7 (65, -88.5) -> (55, -88.5)
  curve K3 (90, -63.5) -> (65, -88.5)
  line L8 (90, -53.5) -> (90, -63.5)
  line L9 (94.1435, -92.6435) -> (78.4501, -76.9501)
  line L10 (61.8584, -76.9501) -> (78.4501, -76.9501)
  line L11 (86.9521, -65.1) -> (88.4, -65.1)
  curve K4 (79.1128, -78.5501) -> (86.9521, -65.1)
  line L12 (61.8584, -78.5501) -> (79.1128, -78.5501)
  curve K5 (88.4, -63.5) -> (65, -86.9)
  curve K6 (66.6, -85.4521) -> (79.5815, -78.0815)
  line L13 (66.6, -86.9) -> (66.6, -85.4521)
  point P6 (78.4501, -76.9501)
  point P13 (78.4501, -76.9501)
  coincident P6 P13
  horizontal L10
  dimension "d265" angle L9 L10 = 135
  dimension "d266" = -1.6
  dimension "d267" = -1.6
  dimension "d268" = -1.6
extrude "Estrusione18" cut sketch "Schizzo15" profile of L11 K4 K5 K6 L13 against normal blind 70
sketch "Schizzo16" plane through (0, -15, 0) normal (0, 1, 0) x axis (-1, 0, 0)
  line L1 (-125, -86.9) -> (-125, -88.5)
  line L2 (-135, -86.9) -> (-125, -86.9)
  line L3 (-135, -83.9) -> (-135, -86.9)
  curve K1 (-135, -83.9) -> (-142.5, -79.9)
  curve K2 (-142.5, -79.9) -> (-160, -86.9)
  line L4 (-160, -88.5) -> (-160, -86.9)
  line L5 (-125, -88.5) -> (-160, -88.5)
  curve K3 (-135, -85.5) -> (-142.5, -81.5)
  curve K4 (-142.5, -81.5) -> (-152.9954, -86.9)
  line L6 (-125, -86.9) -> (-152.9954, -86.9)
  line L7 (-136.6, -83.9) -> (-136.6, -86.9)
  line L8 (-138.6, -84.5053) -> (-138.6, -86.9)
  point P15 (-138.6, -86.9)
  point P16 (-138.6, -84.5053)
  coincident L6 P15
  coincident K3 P16
  perpendicular L6 L8
  dimension "d271" = -1.6
  dimension "d272" = -1.6
  dimension "d673" distance L7 L8 = 2
extrude "Estrusione19" cut sketch "Schizzo16" profile of K3 K4 L6 L8 against normal blind 50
